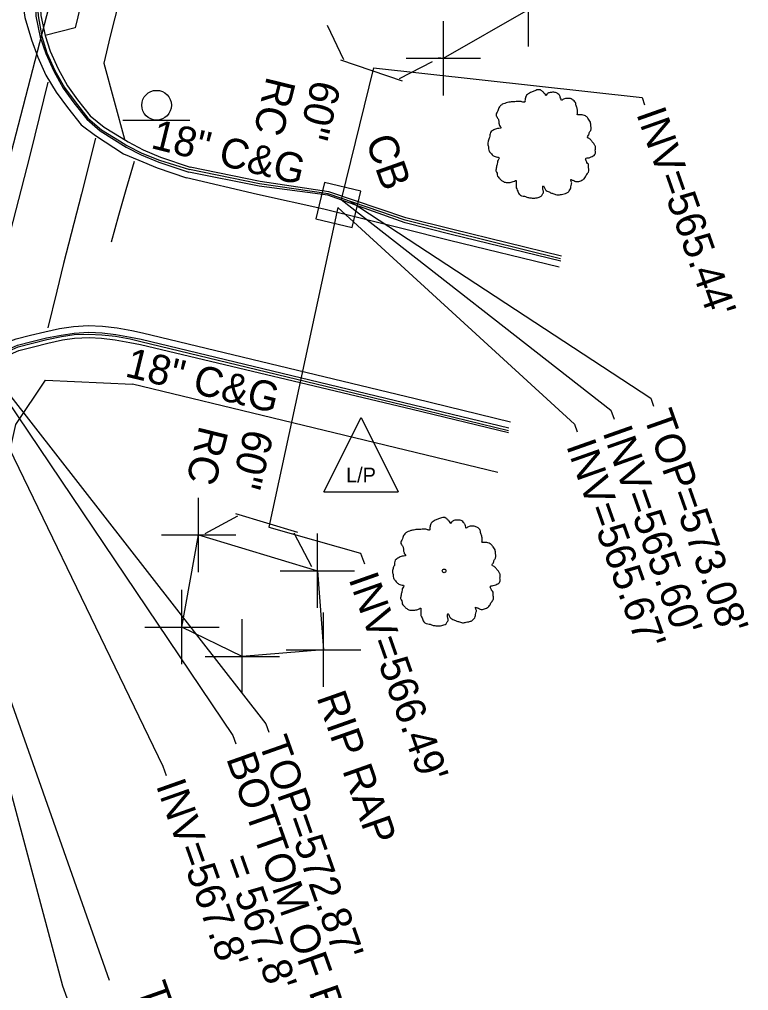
# Model space of a CAD drawing. Extents: x 2004847 to 2009016, y 1134161 to 1140101.
# Drawn here: x 2007657.7 to 2007755.6, y 1138276.6 to 1138407.2 of the extents above; entities that cross this region are included whole.
import ezdxf

# ---------------------------------------------------------------- set-up
doc = ezdxf.new("R2010")
doc.units = 0
for name, color, linetype in [('RD_EX_BldgApp', 7, 'Continuous'), ('RD_EX_Bridge', 7, 'Continuous'), ('RD_EX_Conc', 7, 'Continuous'), ('RD_EX_Curb', 7, 'Continuous'), ('RD_EX_DR_Inlet', 7, 'Continuous'), ('RD_EX_DR_Inlet_txCode', 7, 'Continuous'), ('RD_EX_DR_Pipe', 7, 'Continuous'), ('RD_EX_DR_Pipe_txCode', 7, 'Continuous'), ('RD_EX_DV_Prop_txCode', 7, 'Continuous'), ('RD_EX_Misc', 7, 'Continuous'), ('RD_EX_Pavement_Markings', 7, 'Continuous'), ('RD_EX_Road', 7, 'Continuous'), ('RD_EX_UT', 7, 'Continuous'), ('RD_EX_VEG', 7, 'Continuous'), ('RD_Sketch3', 7, 'Continuous')]:
    doc.layers.add(name, color=color, linetype=linetype)

msp = doc.modelspace()

# ---------------------------------------------------------------- linework, layer by layer
at = {"layer": 'RD_EX_BldgApp'}
msp.add_line((2007671.57, 1138393.65), (2007680.57, 1138393.65), dxfattribs=at)
msp.add_circle((2007676.09, 1138395.68), 2, dxfattribs=at)
at = {"layer": 'RD_EX_Bridge'}
for p, q in [((2007699.03, 1138406.43), (2007701.23, 1138401.82)), ((2007700.79, 1138401.78), (2007709.1, 1138398.96)), ((2007708.74, 1138399.29), (2007713.19, 1138401.55)), ((2007686.68, 1138340.79), (2007695.01, 1138338.26)), ((2007682.61, 1138338.09), (2007687, 1138340.45)), ((2007694.52, 1138338.19), (2007696.89, 1138333.65))]:
    msp.add_line(p, q, dxfattribs=at)
at = {"layer": 'RD_EX_Conc'}
for points in [[(2007738.26, 1138655.07), (2007733.31, 1138640.93), (2007728.47, 1138626.92), (2007723.75, 1138612.71), (2007719.05, 1138598.53), (2007716.98, 1138591.92), (2007712.43, 1138577.64), (2007708, 1138563.33), (2007703.81, 1138548.93), (2007699.73, 1138534.5), (2007695.64, 1138520.08), (2007691.52, 1138505.65), (2007687.52, 1138491.2), (2007683.38, 1138476.78), (2007679.54, 1138462.28), (2007675.72, 1138447.78), (2007671.86, 1138433.28), (2007668.2, 1138418.74), (2007665.14, 1138406.08), (2007661.1, 1138405.05)], [(2007742.93, 1138653.43), (2007737.98, 1138639.3), (2007733.17, 1138625.36), (2007728.45, 1138611.16), (2007723.76, 1138597), (2007721.69, 1138590.39), (2007717.15, 1138576.16), (2007712.72, 1138561.82), (2007708.55, 1138547.52), (2007704.47, 1138533.18), (2007700.28, 1138518.86), (2007696.16, 1138504.42), (2007692.16, 1138489.9), (2007688.15, 1138475.45), (2007684.33, 1138460.93), (2007680.53, 1138446.49), (2007676.69, 1138432.06), (2007673.03, 1138417.53), (2007669.85, 1138404.95), (2007669.01, 1138401.33), (2007671.79, 1138391.11)], [(2007652.89, 1138333.81), (2007655.06, 1138343.26), (2007657.19, 1138352.72), (2007661.14, 1138358.69), (2007672.87, 1138358.18)], [(2007721.93, 1138346.29), (2007686.21, 1138354.95), (2007672.87, 1138358.18)]]:
    msp.add_lwpolyline(points, dxfattribs=at)
at = {"layer": 'RD_EX_Curb'}
for points in [[(2007661.42, 1138422.81), (2007660.4, 1138417.6), (2007659.86, 1138412.85), (2007659.75, 1138410.25), (2007659.86, 1138407.67), (2007660.46, 1138404.84), (2007661.19, 1138402.65), (2007662.27, 1138400.25), (2007663.55, 1138397.96), (2007664.96, 1138396.02), (2007666.71, 1138393.8), (2007668.5, 1138392.22), (2007671.99, 1138390.04), (2007674.01, 1138389.01), (2007676.4, 1138388.01), (2007680.41, 1138386.69)], [(2007661.63, 1138422.76), (2007660.7, 1138417.55), (2007660.1, 1138412.83), (2007659.98, 1138410.28), (2007660.16, 1138407.71), (2007660.67, 1138404.91), (2007661.35, 1138402.73), (2007662.43, 1138400.33), (2007663.73, 1138398.06), (2007665.13, 1138396.15), (2007666.86, 1138393.95), (2007668.67, 1138392.39), (2007671.09, 1138390.88), (2007672.08, 1138390.27), (2007674.11, 1138389.25), (2007676.47, 1138388.27), (2007680.5, 1138387.05)], [(2007662.03, 1138422.66), (2007661.13, 1138417.49), (2007660.53, 1138412.81), (2007660.4, 1138410.33), (2007660.53, 1138407.75), (2007661.1, 1138405.05), (2007661.8, 1138402.95), (2007662.88, 1138400.55), (2007664.12, 1138398.28), (2007665.48, 1138396.42), (2007667.18, 1138394.26), (2007669.02, 1138392.74), (2007671.32, 1138391.35), (2007672.28, 1138390.77), (2007674.28, 1138389.67), (2007676.6, 1138388.7), (2007680.6, 1138387.36)], [(2007730.4, 1138374.7), (2007715.69, 1138378.3), (2007709.51, 1138379.85), (2007699.09, 1138383.59), (2007689.88, 1138384.79), (2007680.41, 1138386.69)], [(2007730.37, 1138375.02), (2007715.74, 1138378.66), (2007709.49, 1138380.2), (2007699.13, 1138383.78), (2007689.9, 1138385.11), (2007680.5, 1138387.05)], [(2007730.5, 1138375.38), (2007715.89, 1138378.98), (2007709.57, 1138380.55), (2007699.24, 1138384.03), (2007689.99, 1138385.42), (2007680.6, 1138387.36)], [(2007642.84, 1138345.21), (2007643.54, 1138347.08), (2007644.3, 1138348.93), (2007645.05, 1138350.62), (2007645.92, 1138352.42), (2007646.68, 1138353.94), (2007647.52, 1138355.39), (2007648.65, 1138357.04), (2007649.65, 1138358.24), (2007650.92, 1138359.55), (2007652.49, 1138360.81), (2007653.95, 1138361.86), (2007655.76, 1138362.7), (2007657.41, 1138363.41), (2007659.34, 1138363.9), (2007661.28, 1138364.39), (2007663.25, 1138364.76), (2007664.99, 1138365), (2007666.98, 1138365.15), (2007668.76, 1138365.05), (2007670.62, 1138364.85), (2007672.59, 1138364.49), (2007674.01, 1138364.23)], [(2007642.98, 1138345.16), (2007643.69, 1138347.02), (2007644.45, 1138348.87), (2007645.24, 1138350.53), (2007646.08, 1138352.35), (2007646.87, 1138353.82), (2007647.69, 1138355.24), (2007648.8, 1138356.92), (2007649.79, 1138358.06), (2007651.05, 1138359.33), (2007652.61, 1138360.61), (2007654.05, 1138361.62), (2007655.86, 1138362.46), (2007657.47, 1138363.18), (2007659.4, 1138363.66), (2007661.34, 1138364.19), (2007663.3, 1138364.58), (2007665, 1138364.83), (2007667, 1138364.89), (2007668.74, 1138364.79), (2007670.58, 1138364.61), (2007672.55, 1138364.25), (2007673.96, 1138363.88)], [(2007643.41, 1138344.99), (2007644.12, 1138346.86), (2007644.89, 1138348.71), (2007645.64, 1138350.34), (2007646.48, 1138352.16), (2007647.26, 1138353.58), (2007648.06, 1138354.94), (2007649.16, 1138356.62), (2007650.05, 1138357.73), (2007651.28, 1138358.96), (2007652.84, 1138360.24), (2007654.24, 1138361.17), (2007656.06, 1138362.01), (2007657.59, 1138362.69), (2007659.53, 1138363.18), (2007661.46, 1138363.68), (2007663.42, 1138364.11), (2007665.04, 1138364.34), (2007667.03, 1138364.44), (2007668.7, 1138364.34), (2007670.5, 1138364.13), (2007672.47, 1138363.77), (2007673.93, 1138363.5)], [(2007674.01, 1138364.23), (2007710.6, 1138355.37), (2007723.45, 1138352.28)], [(2007673.93, 1138363.5), (2007710.42, 1138354.78), (2007723.39, 1138351.67)], [(2007673.96, 1138363.88), (2007710.54, 1138355.05), (2007723.37, 1138351.94)]]:
    msp.add_lwpolyline(points, dxfattribs=at)
at = {"layer": 'RD_EX_DR_Inlet'}
msp.add_line((2007702.37, 1138379.25), (2007703.53, 1138384.11), dxfattribs=at)
msp.add_lwpolyline([(2007702.37, 1138379.25), (2007703.53, 1138384.11), (2007698.67, 1138385.27), (2007697.5, 1138380.41)], close=True, dxfattribs=at)
at = {"layer": 'RD_EX_DR_Inlet_txCode'}
msp.add_line((2007646.14, 1138344.88), (2007669.73, 1138277.99), dxfattribs=at)
for points in [[(2007705.22, 1138400.71), (2007741.34, 1138396.7), (2007741.68, 1138395.74)], [(2007700.91, 1138382.98), (2007737.13, 1138354.68), (2007737.57, 1138353.44)], [(2007702.09, 1138382.78), (2007742.5, 1138356.27), (2007742.87, 1138355.2)], [(2007700.46, 1138381.92), (2007732.26, 1138352.77), (2007732.63, 1138351.73)], [(2007650.15, 1138364.64), (2007686.33, 1138310.93), (2007686.73, 1138309.79)], [(2007650.15, 1138364.64), (2007690.76, 1138312.49), (2007691.16, 1138311.35)], [(2007649.8, 1138362.93), (2007676.94, 1138306.8), (2007677.38, 1138305.55)], [(2007645.79, 1138343.17), (2007663.45, 1138277.25), (2007664.01, 1138275.65)], [(2007691.16, 1138338.95), (2007703.51, 1138335.43), (2007704.01, 1138334.01)]]:
    msp.add_lwpolyline(points, dxfattribs=at)
at = {"layer": 'RD_EX_DR_Pipe'}
for p, q in [((2007650.59, 1138366.33), (2007679.85, 1138479.28)), ((2007705.22, 1138400.71), (2007700.91, 1138382.98)), ((2007700.46, 1138381.92), (2007691.16, 1138338.95))]:
    msp.add_line(p, q, dxfattribs=at)
at = {"layer": 'RD_EX_DV_Prop_txCode'}
for p, q in [((2007726.08, 1138403.57), (2007726.08, 1138413.57)), ((2007714.63, 1138397), (2007714.63, 1138407)), ((2007709.63, 1138402), (2007719.63, 1138402)), ((2007681.74, 1138332.89), (2007681.74, 1138342.89)), ((2007697.7, 1138328.07), (2007697.7, 1138338.07)), ((2007676.74, 1138337.89), (2007686.74, 1138337.89)), ((2007692.7, 1138333.07), (2007702.7, 1138333.07)), ((2007679.5, 1138320.5), (2007679.5, 1138330.5)), ((2007687.6, 1138316.54), (2007687.6, 1138326.54)), ((2007698.52, 1138317.45), (2007698.52, 1138327.45)), ((2007674.5, 1138325.5), (2007684.5, 1138325.5)), ((2007693.52, 1138322.45), (2007703.52, 1138322.45)), ((2007682.6, 1138321.54), (2007692.6, 1138321.54))]:
    msp.add_line(p, q, dxfattribs=at)
at = {"layer": 'RD_EX_Misc'}
for points in [[(2007713.99, 1138402.09), (2007714.63, 1138402), (2007726.08, 1138408.57), (2007719.35, 1138418.83), (2007719.64, 1138419.43)], [(2007697.7, 1138333.07), (2007698.52, 1138322.45), (2007687.6, 1138321.54), (2007679.5, 1138325.5), (2007681.74, 1138337.89), (2007697.7, 1138333.07)]]:
    msp.add_lwpolyline(points, dxfattribs=at)
at = {"layer": 'RD_EX_Pavement_Markings'}
for points in [[(2007653.51, 1138367.12), (2007654.39, 1138370.56), (2007656.45, 1138378.66), (2007658.71, 1138387.35), (2007659.19, 1138389.27), (2007661.53, 1138398.76)], [(2007667.88, 1138391.25), (2007666, 1138383.76), (2007663.56, 1138374.41), (2007662.66, 1138370.65), (2007661.47, 1138365.73)], [(2007670.05, 1138377.32), (2007671.02, 1138380.9), (2007672.01, 1138384.36), (2007673.11, 1138388.14)]]:
    msp.add_lwpolyline(points, dxfattribs=at)
at = {"layer": 'RD_EX_Road'}
for points in [[(2007659.56, 1138423.28), (2007658.62, 1138417.86), (2007658, 1138412.93), (2007658, 1138410.04), (2007658.38, 1138407.49), (2007659.28, 1138404.47), (2007660.13, 1138402.13), (2007661.21, 1138399.73), (2007662.61, 1138397.45), (2007664.12, 1138395.37), (2007665.94, 1138393.05), (2007667.88, 1138391.62), (2007671.63, 1138389.16), (2007673.72, 1138388.29), (2007676.18, 1138387.27), (2007680.09, 1138385.93)], [(2007730.21, 1138373.88), (2007715.45, 1138377.5), (2007709.24, 1138379.06), (2007698.57, 1138381.7), (2007689.64, 1138383.68), (2007680.09, 1138385.93)], [(2007640.84, 1138345.98), (2007641.56, 1138347.85), (2007642.32, 1138349.7), (2007643.13, 1138351.5), (2007644, 1138353.3), (2007644.96, 1138355), (2007645.99, 1138356.66), (2007647.25, 1138358.21), (2007648.63, 1138359.54), (2007650.18, 1138360.75), (2007651.88, 1138361.8), (2007653.57, 1138362.73), (2007655.39, 1138363.57), (2007657.2, 1138364.24), (2007659.14, 1138364.73), (2007661.08, 1138365.22), (2007663.03, 1138365.65), (2007664.92, 1138365.92), (2007666.91, 1138366.07), (2007668.83, 1138365.97), (2007670.77, 1138365.74), (2007672.74, 1138365.38), (2007674.18, 1138365.07)], [(2007674.18, 1138365.07), (2007710.83, 1138356.25), (2007723.65, 1138353.1)]]:
    msp.add_lwpolyline(points, dxfattribs=at)
at = {"layer": 'RD_EX_UT'}
for p, q in [((2007698.56, 1138343.66), (2007703.56, 1138353.66)), ((2007703.56, 1138353.66), (2007708.56, 1138343.66)), ((2007698.56, 1138343.66), (2007708.56, 1138343.66))]:
    msp.add_line(p, q, dxfattribs=at)
at = {"layer": 'RD_EX_VEG'}
for centre, radius in [((2007714.73, 1138333.05), 0.25), ((2007714.72, 1138333.03), 0.0001)]:
    msp.add_circle(centre, radius, dxfattribs=at)
for points in [[(2007727.67, 1138397.75), (2007727.37, 1138397.77), (2007727.04, 1138397.67), (2007726.79, 1138397.57), (2007726.57, 1138397.5), (2007726.34, 1138397.4), (2007726.04, 1138397.22), (2007725.82, 1138397.02), (2007725.69, 1138396.77), (2007725.64, 1138396.55), (2007725.59, 1138396.28), (2007725.59, 1138396.1), (2007725.47, 1138396.08), (2007725.32, 1138396.1), (2007725.07, 1138396.18), (2007724.82, 1138396.18), (2007724.57, 1138396.18), (2007724.22, 1138396.15), (2007723.87, 1138396.15), (2007723.6, 1138396.1), (2007723.27, 1138396.05), (2007722.9, 1138395.93), (2007722.55, 1138395.8), (2007722.25, 1138395.55), (2007722, 1138395.08), (2007721.87, 1138394.73), (2007721.72, 1138394.48), (2007721.87, 1138394.03), (2007722.05, 1138393.68), (2007722.07, 1138393.48), (2007722.15, 1138393.05), (2007722.25, 1138392.83), (2007722.37, 1138392.63), (2007722.3, 1138392.6), (2007721.92, 1138392.55), (2007721.62, 1138392.45), (2007721.2, 1138392.23), (2007720.97, 1138392), (2007720.87, 1138391.68), (2007720.85, 1138391.33), (2007720.75, 1138391.13), (2007720.67, 1138390.85), (2007720.65, 1138390.78), (2007720.6, 1138390.45), (2007720.7, 1138390), (2007720.72, 1138389.65), (2007720.85, 1138389.43), (2007721, 1138389.25), (2007721.17, 1138389), (2007721.57, 1138388.78), (2007721.9, 1138388.68), (2007722.1, 1138388.65), (2007721.92, 1138388.15), (2007721.87, 1138387.8), (2007721.75, 1138387.4), (2007721.75, 1138387.33), (2007721.7, 1138386.85), (2007721.85, 1138386.53), (2007721.92, 1138386.15), (2007722.1, 1138385.93), (2007722.37, 1138385.63), (2007722.7, 1138385.4), (2007723.2, 1138385.28), (2007723.6, 1138385.3), (2007724.17, 1138385.48), (2007724.42, 1138385.55), (2007724.4, 1138385.38), (2007724.42, 1138385.01), (2007724.42, 1138384.58), (2007724.57, 1138384.26), (2007724.67, 1138383.98), (2007724.82, 1138383.73), (2007725.14, 1138383.51), (2007725.54, 1138383.43), (2007725.97, 1138383.28), (2007726.42, 1138383.21), (2007726.92, 1138383.18), (2007727.52, 1138383.33), (2007727.79, 1138383.46), (2007727.89, 1138383.63), (2007728.09, 1138384.01), (2007728.04, 1138384.23), (2007728.07, 1138384.83), (2007728.17, 1138384.66), (2007728.34, 1138384.31), (2007728.84, 1138384.01), (2007729.24, 1138383.83), (2007729.72, 1138383.68), (2007730.02, 1138383.61), (2007730.49, 1138383.68), (2007730.87, 1138383.76), (2007731.24, 1138383.88), (2007731.54, 1138384.16), (2007731.72, 1138384.43), (2007731.77, 1138384.71), (2007731.84, 1138385.08), (2007731.89, 1138385.25)], [(2007731.89, 1138385.25), (2007731.82, 1138385.43), (2007731.77, 1138385.68), (2007731.84, 1138385.65), (2007732.02, 1138385.6), (2007732.29, 1138385.48), (2007732.52, 1138385.4), (2007732.84, 1138385.43), (2007733.12, 1138385.53), (2007733.57, 1138385.8), (2007733.84, 1138386.28), (2007734.12, 1138386.68), (2007734.19, 1138387), (2007734.14, 1138387.23), (2007734.12, 1138387.73), (2007733.92, 1138387.98), (2007733.87, 1138388.1), (2007733.77, 1138388.5), (2007733.84, 1138388.55), (2007734.12, 1138388.6), (2007734.49, 1138388.73), (2007734.77, 1138388.85), (2007734.99, 1138389.03), (2007735.07, 1138389.25), (2007735.04, 1138389.65), (2007735.09, 1138390.05), (2007735.02, 1138390.2), (2007734.92, 1138390.35), (2007734.84, 1138390.55), (2007734.69, 1138390.7), (2007734.59, 1138390.85), (2007734.49, 1138390.95), (2007734.37, 1138391.1), (2007734.19, 1138391.23), (2007734.04, 1138391.28), (2007733.99, 1138391.43), (2007734.14, 1138391.63), (2007734.19, 1138391.73), (2007734.22, 1138391.95), (2007734.44, 1138392.3), (2007734.49, 1138392.7), (2007734.44, 1138393.13), (2007734.39, 1138393.4), (2007734.24, 1138393.68), (2007734.04, 1138393.93), (2007733.92, 1138394.1), (2007733.74, 1138394.23), (2007733.42, 1138394.35), (2007733.17, 1138394.4), (2007732.82, 1138394.4), (2007732.62, 1138394.45), (2007732.64, 1138394.5), (2007732.64, 1138394.65), (2007732.64, 1138394.93), (2007732.57, 1138395.38), (2007732.42, 1138395.88), (2007732.42, 1138395.9), (2007732.32, 1138396.15), (2007732.09, 1138396.35), (2007731.92, 1138396.45), (2007731.72, 1138396.58), (2007731.47, 1138396.6), (2007731.17, 1138396.6), (2007730.89, 1138396.55), (2007730.69, 1138396.45), (2007730.52, 1138396.33), (2007730.44, 1138396.48), (2007730.34, 1138396.77), (2007730.29, 1138396.92), (2007730.14, 1138397.1), (2007729.92, 1138397.3), (2007729.47, 1138397.42), (2007728.84, 1138397.35), (2007728.54, 1138397.15), (2007728.39, 1138396.97), (2007728.34, 1138397.1), (2007728.14, 1138397.3), (2007728.04, 1138397.47), (2007727.87, 1138397.6), (2007727.72, 1138397.7), (2007727.62, 1138397.75)], [(2007714.86, 1138340.22), (2007714.56, 1138340.24), (2007714.24, 1138340.14), (2007713.99, 1138340.04), (2007713.76, 1138339.97), (2007713.54, 1138339.87), (2007713.24, 1138339.69), (2007713.01, 1138339.49), (2007712.89, 1138339.24), (2007712.84, 1138339.02), (2007712.79, 1138338.74), (2007712.79, 1138338.57), (2007712.66, 1138338.54), (2007712.51, 1138338.57), (2007712.26, 1138338.64), (2007712.01, 1138338.64), (2007711.76, 1138338.64), (2007711.41, 1138338.62), (2007711.06, 1138338.62), (2007710.79, 1138338.57), (2007710.46, 1138338.52), (2007710.09, 1138338.39), (2007709.74, 1138338.27), (2007709.44, 1138338.02), (2007709.19, 1138337.54), (2007709.06, 1138337.19), (2007708.91, 1138336.94), (2007709.06, 1138336.49), (2007709.24, 1138336.14), (2007709.26, 1138335.94), (2007709.34, 1138335.52), (2007709.44, 1138335.29), (2007709.56, 1138335.09), (2007709.49, 1138335.07), (2007709.11, 1138335.02), (2007708.81, 1138334.92), (2007708.39, 1138334.69), (2007708.16, 1138334.47), (2007708.06, 1138334.14), (2007708.04, 1138333.79), (2007707.94, 1138333.59), (2007707.87, 1138333.32), (2007707.84, 1138333.24), (2007707.79, 1138332.92), (2007707.89, 1138332.47), (2007707.92, 1138332.12), (2007708.04, 1138331.89), (2007708.19, 1138331.72), (2007708.36, 1138331.47), (2007708.76, 1138331.24), (2007709.09, 1138331.14), (2007709.29, 1138331.12), (2007709.11, 1138330.62), (2007709.06, 1138330.27), (2007708.94, 1138329.87), (2007708.94, 1138329.79), (2007708.89, 1138329.32), (2007709.04, 1138329), (2007709.11, 1138328.62), (2007709.29, 1138328.4), (2007709.56, 1138328.1), (2007709.89, 1138327.87), (2007710.39, 1138327.75), (2007710.79, 1138327.77), (2007711.36, 1138327.95), (2007711.61, 1138328.02), (2007711.59, 1138327.85), (2007711.61, 1138327.47), (2007711.61, 1138327.05), (2007711.76, 1138326.72), (2007711.86, 1138326.45), (2007712.01, 1138326.2), (2007712.34, 1138325.97), (2007712.74, 1138325.9), (2007713.16, 1138325.75), (2007713.61, 1138325.67), (2007714.11, 1138325.65), (2007714.71, 1138325.8), (2007714.99, 1138325.92), (2007715.09, 1138326.1), (2007715.29, 1138326.47), (2007715.24, 1138326.7), (2007715.26, 1138327.3), (2007715.36, 1138327.12), (2007715.54, 1138326.77), (2007716.04, 1138326.47), (2007716.44, 1138326.3), (2007716.91, 1138326.15), (2007717.21, 1138326.07), (2007717.69, 1138326.15), (2007718.06, 1138326.22), (2007718.44, 1138326.35), (2007718.74, 1138326.62), (2007718.91, 1138326.9), (2007718.96, 1138327.17), (2007719.04, 1138327.55), (2007719.09, 1138327.72)], [(2007719.09, 1138327.72), (2007719.01, 1138327.9), (2007718.96, 1138328.15), (2007719.04, 1138328.12), (2007719.21, 1138328.07), (2007719.48, 1138327.95), (2007719.71, 1138327.87), (2007720.03, 1138327.9), (2007720.31, 1138328), (2007720.76, 1138328.27), (2007721.03, 1138328.75), (2007721.31, 1138329.15), (2007721.38, 1138329.47), (2007721.33, 1138329.69), (2007721.31, 1138330.19), (2007721.11, 1138330.44), (2007721.06, 1138330.57), (2007720.96, 1138330.97), (2007721.03, 1138331.02), (2007721.31, 1138331.07), (2007721.68, 1138331.19), (2007721.96, 1138331.32), (2007722.18, 1138331.49), (2007722.26, 1138331.72), (2007722.23, 1138332.12), (2007722.28, 1138332.52), (2007722.21, 1138332.67), (2007722.11, 1138332.82), (2007722.03, 1138333.02), (2007721.88, 1138333.17), (2007721.78, 1138333.32), (2007721.68, 1138333.42), (2007721.56, 1138333.57), (2007721.38, 1138333.69), (2007721.23, 1138333.74), (2007721.18, 1138333.89), (2007721.33, 1138334.09), (2007721.38, 1138334.19), (2007721.41, 1138334.42), (2007721.63, 1138334.77), (2007721.68, 1138335.17), (2007721.63, 1138335.59), (2007721.58, 1138335.87), (2007721.43, 1138336.14), (2007721.23, 1138336.39), (2007721.11, 1138336.57), (2007720.93, 1138336.69), (2007720.61, 1138336.82), (2007720.36, 1138336.87), (2007720.01, 1138336.87), (2007719.81, 1138336.92), (2007719.83, 1138336.97), (2007719.83, 1138337.12), (2007719.83, 1138337.39), (2007719.76, 1138337.84), (2007719.61, 1138338.34), (2007719.61, 1138338.37), (2007719.51, 1138338.62), (2007719.29, 1138338.82), (2007719.11, 1138338.92), (2007718.91, 1138339.04), (2007718.66, 1138339.07), (2007718.36, 1138339.07), (2007718.09, 1138339.02), (2007717.89, 1138338.92), (2007717.71, 1138338.79), (2007717.64, 1138338.94), (2007717.54, 1138339.24), (2007717.49, 1138339.39), (2007717.34, 1138339.57), (2007717.11, 1138339.77), (2007716.66, 1138339.89), (2007716.04, 1138339.82), (2007715.74, 1138339.62), (2007715.59, 1138339.44), (2007715.54, 1138339.57), (2007715.34, 1138339.77), (2007715.24, 1138339.94), (2007715.06, 1138340.07), (2007714.91, 1138340.17), (2007714.81, 1138340.22)]]:
    msp.add_spline(points, degree=3, dxfattribs=at)

# ---------------------------------------------------------------- texts
at = {"layer": 'RD_EX_DR_Inlet_txCode'}
for s, p in [("INV=565.44'", (2007740.52, 1138394.55)), ('CB', (2007704.14, 1138390.95)), ("TOP=573.08'", (2007741.48, 1138353.89)), ("INV=565.60'", (2007735.99, 1138351.73)), ("INV=565.67'", (2007731.1, 1138349.9)), ("INV=566.49'", (2007701.86, 1138331.99)), ("TOP=572.87'", (2007689.76, 1138310.01)), ('BOTTOM OF BOX', (2007685.41, 1138307.83)), ("INV=567.8'", (2007675.97, 1138304.22)), ("= 567.8'", (2007684.95, 1138294.1)), ("TOP=573.46'", (2007673.42, 1138276.95))]:
    msp.add_text(s, height=4, rotation=289.4494, dxfattribs=at).set_placement(p)
at = {"layer": 'RD_EX_DR_Pipe_txCode'}
for s, p in [('RC', (2007690.94, 1138399.69)), ('60"', (2007697.02, 1138399.26)), ('RC', (2007681.89, 1138352.72)), ('60"', (2007687.97, 1138352.3))]:
    msp.add_text(s, height=4, rotation=256.1738, dxfattribs=at).set_placement(p)
at = {"layer": 'RD_EX_UT'}
msp.add_text('L/P', height=2, dxfattribs=at).set_placement((2007701.55, 1138344.94))
at = {"layer": 'RD_Sketch3'}
for s, rotation, p in [('18" C&G', 346.144, (2007675.17, 1138389.94)), ('18" C&G', 346.144, (2007671.7, 1138359.24)), ('RIP RAP', 289.4494, (2007697.55, 1138316.05))]:
    msp.add_text(s, height=4, rotation=rotation, dxfattribs=at).set_placement(p)

doc.saveas('drawing.dxf')
